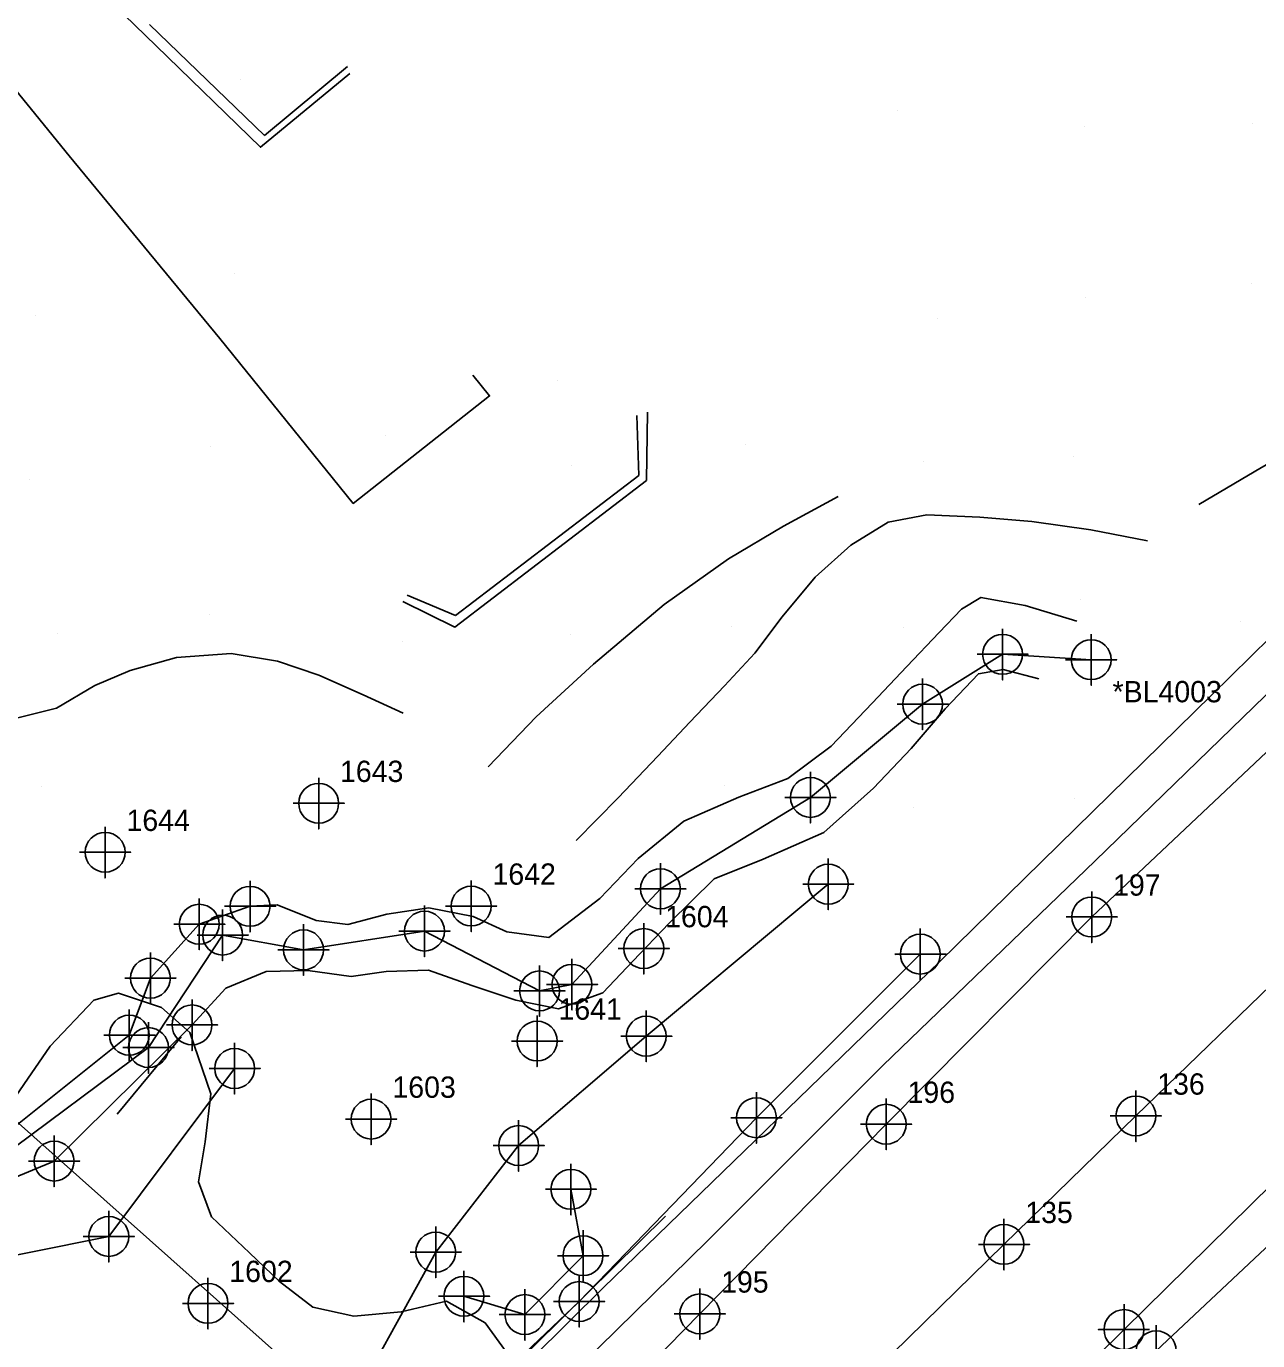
# Model space of a CAD drawing. Extents: x 1497074 to 1501343, y 481943 to 486114.
# Drawn here: x 1498304.9 to 1498449.4, y 484641.5 to 484795.7 of the extents above; entities that cross this region are included whole.
import ezdxf

# ---------------------------------------------------------------- set-up
doc = ezdxf.new("R2010")
doc.units = 0
for name, color, linetype in [('Exist DTM Breakline', 7, 'Continuous'), ('Exist DTM Breakline Cogo Point CELL', 7, 'Continuous'), ('Exist DTM Crownline', 7, 'Continuous'), ('Exist DTM Crownline Cogo Number', 7, 'Continuous'), ('Exist DTM Crownline Cogo Point CELL', 7, 'Continuous'), ('Exist DTM Drainline', 7, 'Continuous'), ('Exist DTM Drainline Cogo Comment', 7, 'Continuous'), ('Exist DTM Drainline Cogo Point CELL', 7, 'Continuous'), ('Exist DTM Regular Point CELL', 7, 'Continuous'), ('Exist DTM Regular Point Cogo Number', 7, 'Continuous'), ('Exist Guardrail', 7, 'Continuous'), ('Exist Roads EOP', 7, 'Continuous'), ('Exist Roads EOP Cogo Number', 7, 'Continuous'), ('Exist Roads EOP Cogo Point CELL', 7, 'Continuous'), ('Exist Roads EOT', 7, 'Continuous'), ('Exist Roads EOT Cogo Point CELL', 7, 'Continuous'), ('PH Exist DTM Boundary', 7, 'Continuous'), ('PH Exist DTM Breakline', 7, 'Continuous'), ('PH Exist DTM Obscure Area', 7, 'Continuous'), ('PH Exist DTM Point', 7, 'Continuous')]:
    doc.layers.add(name, color=color, linetype=linetype)

msp = doc.modelspace()

# ---------------------------------------------------------------- linework, layer by layer
at = {"layer": 'Exist DTM Breakline'}
for points in [[(1498398.97, 484695.06), (1498377.62, 484677.22), (1498362.65, 484664.38), (1498352.92, 484651.88), (1498341.4, 484630.97), (1498319.66, 484605.39), (1498294.63, 484580.7), (1498267.47, 484556.87), (1498247.84, 484542.39), (1498225.77, 484518.58)], [(1498282.88, 484689.25), (1498293.31, 484665.67), (1498300.1, 484663.88), (1498316.97, 484677.34), (1498319.45, 484684.03), (1498325.18, 484690.36), (1498331.14, 484692.46)], [(1498231.12, 484516.09), (1498254.57, 484537.6), (1498277.62, 484558.98), (1498300.74, 484581.31), (1498327.42, 484605.51), (1498348.5, 484625.92), (1498369.75, 484646.08), (1498390.54, 484667.65), (1498409.77, 484686.85)], [(1498324.33, 484678.54), (1498308.15, 484662.56), (1498298.41, 484658.52), (1498293.57, 484658), (1498288.84, 484660.48), (1498279.47, 484663.46)], [(1498269.6, 484655.18), (1498295.66, 484649.92), (1498314.57, 484653.72), (1498329.33, 484673.43)], [(1498467.53, 484668.57), (1498437.44, 484640.31), (1498419.38, 484622.3)], [(1498368.78, 484659.25), (1498370.2, 484651.46), (1498363.38, 484644.55), (1498356.23, 484646.7)]]:
    msp.add_lwpolyline(points, dxfattribs=at)
at = {"layer": 'Exist DTM Breakline Cogo Point CELL'}
for points in [[(1498398.97, 484698.06), (1498398.97, 484692.06), (1498398.97, 484695.06), (1498401.97, 484695.06), (1498395.97, 484695.06)], [(1498331.14, 484695.46), (1498331.14, 484689.46), (1498331.14, 484692.46), (1498334.14, 484692.46), (1498328.14, 484692.46)], [(1498325.18, 484693.36), (1498325.18, 484687.36), (1498325.18, 484690.36), (1498328.18, 484690.36), (1498322.18, 484690.36)], [(1498409.77, 484689.85), (1498409.77, 484683.85), (1498409.77, 484686.85), (1498412.77, 484686.85), (1498406.77, 484686.85)], [(1498319.45, 484687.03), (1498319.45, 484681.03), (1498319.45, 484684.03), (1498322.45, 484684.03), (1498316.45, 484684.03)], [(1498316.97, 484680.34), (1498316.97, 484674.34), (1498316.97, 484677.34), (1498319.97, 484677.34), (1498313.97, 484677.34)], [(1498324.33, 484681.54), (1498324.33, 484675.54), (1498324.33, 484678.54), (1498327.33, 484678.54), (1498321.33, 484678.54)], [(1498377.62, 484680.22), (1498377.62, 484674.22), (1498377.62, 484677.22), (1498380.62, 484677.22), (1498374.62, 484677.22)], [(1498329.33, 484676.43), (1498329.33, 484670.43), (1498329.33, 484673.43), (1498332.33, 484673.43), (1498326.33, 484673.43)], [(1498390.54, 484670.65), (1498390.54, 484664.65), (1498390.54, 484667.65), (1498393.54, 484667.65), (1498387.54, 484667.65)], [(1498362.65, 484667.38), (1498362.65, 484661.38), (1498362.65, 484664.38), (1498365.65, 484664.38), (1498359.65, 484664.38)], [(1498308.15, 484665.56), (1498308.15, 484659.56), (1498308.15, 484662.56), (1498311.15, 484662.56), (1498305.15, 484662.56)], [(1498368.78, 484662.25), (1498368.78, 484656.25), (1498368.78, 484659.25), (1498371.78, 484659.25), (1498365.78, 484659.25)], [(1498314.57, 484656.72), (1498314.57, 484650.72), (1498314.57, 484653.72), (1498317.57, 484653.72), (1498311.57, 484653.72)], [(1498352.92, 484654.88), (1498352.92, 484648.88), (1498352.92, 484651.88), (1498355.92, 484651.88), (1498349.92, 484651.88)], [(1498370.2, 484654.46), (1498370.2, 484648.46), (1498370.2, 484651.46), (1498373.2, 484651.46), (1498367.2, 484651.46)], [(1498356.23, 484649.7), (1498356.23, 484643.7), (1498356.23, 484646.7), (1498359.23, 484646.7), (1498353.23, 484646.7)], [(1498369.75, 484649.08), (1498369.75, 484643.08), (1498369.75, 484646.08), (1498372.75, 484646.08), (1498366.75, 484646.08)], [(1498363.38, 484647.55), (1498363.38, 484641.55), (1498363.38, 484644.55), (1498366.38, 484644.55), (1498360.38, 484644.55)], [(1498437.44, 484643.31), (1498437.44, 484637.31), (1498437.44, 484640.31), (1498440.44, 484640.31), (1498434.44, 484640.31)]]:
    msp.add_lwpolyline(points, dxfattribs=at)
for centre in [(1498398.97, 484695.06), (1498331.14, 484692.46), (1498325.18, 484690.36), (1498409.77, 484686.85), (1498319.45, 484684.03), (1498324.33, 484678.54), (1498316.97, 484677.34), (1498377.62, 484677.22), (1498329.33, 484673.43), (1498390.54, 484667.65), (1498362.65, 484664.38), (1498308.15, 484662.56), (1498368.78, 484659.25), (1498314.57, 484653.72), (1498352.92, 484651.88), (1498370.2, 484651.46), (1498356.23, 484646.7), (1498369.75, 484646.08), (1498363.38, 484644.55), (1498437.44, 484640.31)]:
    msp.add_circle(centre, 2.34, dxfattribs=at)
at = {"layer": 'Exist DTM Crownline'}
msp.add_lwpolyline([(1498174.51, 484418.76), (1498211.76, 484454.63), (1498248.88, 484490.3), (1498287.28, 484525.89), (1498324.11, 484560.63), (1498360.29, 484595.61), (1498397.16, 484630.83), (1498419.58, 484652.79), (1498435.06, 484667.86), (1498471.56, 484703.24), (1498507.82, 484739.07), (1498544.95, 484775.1), (1498579.44, 484811.19), (1498593.31, 484825.81), (1498614.8, 484848.72), (1498648.9, 484888.1), (1498682.16, 484928.34), (1498714.31, 484969.37), (1498734.43, 484994.62)], dxfattribs=at)
at = {"layer": 'Exist DTM Crownline Cogo Point CELL'}
for points in [[(1498435.06, 484670.86), (1498435.06, 484664.86), (1498435.06, 484667.86), (1498438.06, 484667.86), (1498432.06, 484667.86)], [(1498419.58, 484655.79), (1498419.58, 484649.79), (1498419.58, 484652.79), (1498422.58, 484652.79), (1498416.58, 484652.79)]]:
    msp.add_lwpolyline(points, dxfattribs=at)
for centre in [(1498435.06, 484667.86), (1498419.58, 484652.79)]:
    msp.add_circle(centre, 2.34, dxfattribs=at)
at = {"layer": 'Exist DTM Drainline'}
msp.add_lwpolyline([(1498429.82, 484721.4), (1498419.42, 484722.03), (1498410.04, 484716.18), (1498396.88, 484705.24), (1498379.28, 484694.51), (1498368.9, 484683.3), (1498365.1, 484682.53), (1498351.6, 484689.55), (1498337.41, 484687.35), (1498327.92, 484689.08), (1498319.22, 484675.88), (1498301.55, 484662.75), (1498296.33, 484661.35), (1498291.18, 484665.18), (1498283.03, 484681.58), (1498277.65, 484691.38)], dxfattribs=at)
at = {"layer": 'Exist DTM Drainline Cogo Point CELL'}
for points in [[(1498419.42, 484725.03), (1498419.42, 484719.03), (1498419.42, 484722.03), (1498422.42, 484722.03), (1498416.42, 484722.03)], [(1498429.82, 484724.4), (1498429.82, 484718.4), (1498429.82, 484721.4), (1498432.82, 484721.4), (1498426.82, 484721.4)], [(1498410.04, 484719.18), (1498410.04, 484713.18), (1498410.04, 484716.18), (1498413.04, 484716.18), (1498407.04, 484716.18)], [(1498396.88, 484708.24), (1498396.88, 484702.24), (1498396.88, 484705.24), (1498399.88, 484705.24), (1498393.88, 484705.24)], [(1498379.28, 484697.51), (1498379.28, 484691.51), (1498379.28, 484694.51), (1498382.28, 484694.51), (1498376.28, 484694.51)], [(1498327.92, 484692.08), (1498327.92, 484686.08), (1498327.92, 484689.08), (1498330.92, 484689.08), (1498324.92, 484689.08)], [(1498351.6, 484692.55), (1498351.6, 484686.55), (1498351.6, 484689.55), (1498354.6, 484689.55), (1498348.6, 484689.55)], [(1498337.41, 484690.35), (1498337.41, 484684.35), (1498337.41, 484687.35), (1498340.41, 484687.35), (1498334.41, 484687.35)], [(1498365.1, 484685.53), (1498365.1, 484679.53), (1498365.1, 484682.53), (1498368.1, 484682.53), (1498362.1, 484682.53)], [(1498368.9, 484686.3), (1498368.9, 484680.3), (1498368.9, 484683.3), (1498371.9, 484683.3), (1498365.9, 484683.3)], [(1498319.22, 484678.88), (1498319.22, 484672.88), (1498319.22, 484675.88), (1498322.22, 484675.88), (1498316.22, 484675.88)]]:
    msp.add_lwpolyline(points, dxfattribs=at)
for centre in [(1498419.42, 484722.03), (1498429.82, 484721.4), (1498410.04, 484716.18), (1498396.88, 484705.24), (1498379.28, 484694.51), (1498327.92, 484689.08), (1498351.6, 484689.55), (1498337.41, 484687.35), (1498368.9, 484683.3), (1498365.1, 484682.53), (1498319.22, 484675.88)]:
    msp.add_circle(centre, 2.34, dxfattribs=at)
at = {"layer": 'Exist DTM Regular Point CELL'}
for points in [[(1498339.19, 484707.55), (1498339.19, 484701.55), (1498339.19, 484704.55), (1498342.19, 484704.55), (1498336.19, 484704.55)], [(1498314.14, 484701.8), (1498314.14, 484695.8), (1498314.14, 484698.8), (1498317.14, 484698.8), (1498311.14, 484698.8)], [(1498357.08, 484695.49), (1498357.08, 484689.49), (1498357.08, 484692.49), (1498360.08, 484692.49), (1498354.08, 484692.49)], [(1498377.33, 484690.5), (1498377.33, 484684.5), (1498377.33, 484687.5), (1498380.33, 484687.5), (1498374.33, 484687.5)], [(1498364.82, 484679.65), (1498364.82, 484673.65), (1498364.82, 484676.65), (1498367.82, 484676.65), (1498361.82, 484676.65)], [(1498345.34, 484670.49), (1498345.34, 484664.49), (1498345.34, 484667.49), (1498348.34, 484667.49), (1498342.34, 484667.49)], [(1498326.2, 484648.87), (1498326.2, 484642.87), (1498326.2, 484645.87), (1498329.2, 484645.87), (1498323.2, 484645.87)]]:
    msp.add_lwpolyline(points, dxfattribs=at)
for centre in [(1498339.19, 484704.55), (1498314.14, 484698.8), (1498357.08, 484692.49), (1498377.33, 484687.5), (1498364.82, 484676.65), (1498345.34, 484667.49), (1498326.2, 484645.87)]:
    msp.add_circle(centre, 2.34, dxfattribs=at)
at = {"layer": 'Exist Guardrail'}
msp.add_line((1498379.88, 484656.12), (1498358.55, 484635.05), dxfattribs=at)
at = {"layer": 'Exist Roads EOP'}
msp.add_lwpolyline([(1498165.98, 484428.62), (1498180, 484442.69), (1498201.86, 484464.11), (1498239.3, 484499.9), (1498276.43, 484536.47), (1498313.13, 484573.18), (1498338.89, 484599.2), (1498349.09, 484609.46), (1498368.89, 484629.31), (1498383.9, 484644.63), (1498405.77, 484666.89), (1498429.88, 484691.21), (1498457.88, 484717.62), (1498496.23, 484753.16), (1498535.42, 484789.23), (1498556.84, 484809.01), (1498564.6, 484818.66), (1498566.38, 484823.54), (1498565.95, 484832.29), (1498567.61, 484834.53), (1498567.66, 484834.73)], dxfattribs=at)
at = {"layer": 'Exist Roads EOP Cogo Point CELL'}
for points in [[(1498429.88, 484694.21), (1498429.88, 484688.21), (1498429.88, 484691.21), (1498432.88, 484691.21), (1498426.88, 484691.21)], [(1498405.77, 484669.89), (1498405.77, 484663.89), (1498405.77, 484666.89), (1498408.77, 484666.89), (1498402.77, 484666.89)], [(1498383.9, 484647.63), (1498383.9, 484641.63), (1498383.9, 484644.63), (1498386.9, 484644.63), (1498380.9, 484644.63)]]:
    msp.add_lwpolyline(points, dxfattribs=at)
for centre in [(1498429.88, 484691.21), (1498405.77, 484666.89), (1498383.9, 484644.63)]:
    msp.add_circle(centre, 2.34, dxfattribs=at)
at = {"layer": 'Exist Roads EOT'}
msp.add_lwpolyline([(1498476.1, 484684.28), (1498463.39, 484672.07), (1498433.67, 484642.79), (1498415.98, 484625.26), (1498376.81, 484588.09)], dxfattribs=at)
at = {"layer": 'Exist Roads EOT Cogo Point CELL'}
msp.add_lwpolyline([(1498433.67, 484645.79), (1498433.67, 484639.79), (1498433.67, 484642.79), (1498430.67, 484642.79), (1498436.67, 484642.79)], dxfattribs=at)
msp.add_circle((1498433.67, 484642.79), 2.34, dxfattribs=at)
at = {"layer": 'PH Exist DTM Boundary'}
for points in [[(1498186.43, 484771.69), (1498560.82, 484438.23), (1498782.89, 484653.31), (1498924.23, 484841.06), (1498545.19, 485168.9), (1498406.94, 484985.26)], [(1497810.36, 484407.45), (1498181.14, 484070.49), (1498560.82, 484438.23), (1498186.43, 484771.69)]]:
    msp.add_lwpolyline(points, close=True, dxfattribs=at)
at = {"layer": 'PH Exist DTM Breakline'}
for p, q in [((1498332.85, 484782.92), (1498319.33, 484795.95)), ((1498342.56, 484790.99), (1498332.85, 484782.92)), ((1498376.51, 484750.06), (1498376.75, 484743)), ((1498376.75, 484743), (1498355.25, 484726.6)), ((1498355.25, 484726.6), (1498349.56, 484728.98))]:
    msp.add_line(p, q, dxfattribs=at)
for points in [[(1498359.22, 484628.11), (1498384.86, 484653.26), (1498405.36, 484673.77), (1498430.29, 484697.78), (1498443.63, 484710.75), (1498464.77, 484731.29), (1498490.84, 484757.11), (1498497.71, 484764.47), (1498519.45, 484785.49), (1498553.87, 484820.26), (1498564.01, 484831.41), (1498565.79, 484832.49)], [(1498357.29, 484754.77), (1498359.24, 484752.36), (1498343.24, 484739.73), (1498327.61, 484759.07), (1498309.91, 484780.52), (1498294.59, 484799.39), (1498283.42, 484812.17), (1498280.07, 484815.31), (1498276.09, 484818.03)], [(1498312.58, 484800.8), (1498320.11, 484793.44), (1498332.36, 484781.53), (1498342.85, 484790.18)], [(1498516.8, 484789.57), (1498514.61, 484786.75), (1498494.45, 484766.74), (1498466.99, 484739.94), (1498443.94, 484717.22), (1498412.06, 484686), (1498372.6, 484647.73), (1498355.93, 484631.24)], [(1498442.44, 484739.6), (1498449.8, 484743.97), (1498457.64, 484748.4), (1498465.41, 484752.75), (1498474.14, 484759.78), (1498487.03, 484768.95), (1498495.81, 484775.13), (1498502.49, 484779.15)], [(1498349.08, 484728.23), (1498355.15, 484725.22), (1498377.65, 484742.43), (1498377.77, 484750.43)], [(1498359.09, 484708.81), (1498364.69, 484714.7), (1498371.41, 484720.87), (1498379.71, 484727.88), (1498387.25, 484733.23), (1498393.71, 484737.06), (1498400.13, 484740.56)], [(1498436.42, 484735.34), (1498429.79, 484736.62), (1498422.85, 484737.62), (1498416.76, 484738.14), (1498410.55, 484738.38), (1498406.01, 484737.54), (1498401.63, 484734.84), (1498397.45, 484731.1), (1498393.58, 484726.43), (1498390.34, 484722.16), (1498386.79, 484718.33), (1498382.72, 484714.05), (1498378.97, 484710.09), (1498374.32, 484705.2), (1498369.41, 484700.19)], [(1498428.15, 484725.9), (1498422.08, 484727.77), (1498416.87, 484728.7), (1498414.6, 484727.34)], [(1498331.14, 484692.46), (1498334.32, 484692.65), (1498338.89, 484690.81), (1498342.61, 484690.31), (1498347.2, 484691.55), (1498352.11, 484692.3), (1498357.32, 484691.26), (1498361.26, 484689.45), (1498366.17, 484688.79), (1498372.19, 484693.36), (1498376.67, 484698.08), (1498382.01, 484702.44), (1498388.48, 484705.26), (1498394.22, 484707.46), (1498399.32, 484711.25), (1498404.12, 484716.3), (1498408.2, 484720.6), (1498411.99, 484724.59), (1498414.6, 484727.34)], [(1498269.88, 484709.47), (1498274.5, 484713.94), (1498279.79, 484716.29), (1498284.72, 484716.72), (1498290.58, 484715.56), (1498296.68, 484714.5), (1498302.03, 484714.12), (1498308.44, 484715.7), (1498312.94, 484718.37), (1498317.08, 484720.14), (1498322.49, 484721.64), (1498328.91, 484722.11), (1498334.34, 484721.22), (1498339.21, 484719.59), (1498344.41, 484717.28), (1498349.09, 484715.14)], [(1498423.67, 484719.14), (1498419.5, 484720.24), (1498416.58, 484719.75), (1498412.67, 484715.64), (1498408.68, 484710.97), (1498404.27, 484706.32), (1498398.45, 484701.12), (1498391.32, 484697.98), (1498385.58, 484695.68), (1498380.3, 484690.49), (1498376.05, 484686.02), (1498372.51, 484682.29), (1498367.34, 484680.43), (1498362.33, 484681.43), (1498357.15, 484683.16), (1498352.07, 484684.96), (1498347.1, 484684.81), (1498343.01, 484684.24), (1498337.91, 484684.94), (1498333.02, 484684.81), (1498328.28, 484682.86), (1498324.33, 484678.54)], [(1498323.04, 484677.13), (1498315.56, 484668.05)]]:
    msp.add_lwpolyline(points, dxfattribs=at)
at = {"layer": 'PH Exist DTM Obscure Area'}
for points in [[(1498307.67, 484676.05), (1498312.8, 484681.46), (1498315.7, 484682.25), (1498320.76, 484680.6), (1498324.07, 484677.66), (1498326.55, 484670.45), (1498325.86, 484664.83), (1498325.1, 484660.14), (1498326.63, 484656.03), (1498331.08, 484651.8), (1498334.61, 484648.45), (1498338.49, 484645.41), (1498343.32, 484644.37), (1498348.86, 484644.88), (1498354.17, 484646.11), (1498358.72, 484643.58), (1498361.19, 484640.19), (1498355.63, 484632.52)], [(1498355.63, 484632.52), (1498290.68, 484570.04), (1498257.3, 484537.58), (1498250.31, 484532.74), (1498247.22, 484535.69), (1498242.12, 484540.68), (1498249.39, 484548.29), (1498258.26, 484557.58), (1498264.88, 484564.52), (1498267.78, 484576.18), (1498266.58, 484587.34), (1498261.75, 484599.27), (1498263.15, 484609.32), (1498271.1, 484617.66), (1498279.29, 484626.23), (1498284.85, 484632.06), (1498282.05, 484639.76), (1498283.05, 484646.51), (1498293.08, 484654.8), (1498307.67, 484676.05)]]:
    msp.add_lwpolyline(points, dxfattribs=at)
at = {"layer": 'PH Exist DTM Point'}
for p, q in [((1498330.05, 484789.49), (1498330.05, 484789.49)), ((1498407.05, 484785.89), (1498407.05, 484785.89)), ((1498429.06, 484783.97), (1498429.06, 484783.97)), ((1498448.72, 484784.29), (1498448.72, 484784.29)), ((1498329.32, 484766.75), (1498329.32, 484766.75)), ((1498448.57, 484765.59), (1498448.57, 484765.59)), ((1498429.1, 484763.94), (1498429.1, 484763.94)), ((1498305.96, 484761.82), (1498305.96, 484761.82)), ((1498411.79, 484761.41), (1498411.79, 484761.41)), ((1498367.16, 484754.2), (1498367.16, 484754.2)), ((1498347.03, 484747.71), (1498347.03, 484747.71)), ((1498326.51, 484746.39), (1498326.51, 484746.39)), ((1498389.21, 484746.63), (1498389.21, 484746.63)), ((1498427.73, 484745.24), (1498427.73, 484745.24)), ((1498368.82, 484744.16), (1498368.82, 484744.16)), ((1498410.18, 484744.69), (1498410.18, 484744.69)), ((1498305.28, 484742.49), (1498305.28, 484742.49)), ((1498428.59, 484728.43), (1498428.59, 484728.43)), ((1498326.43, 484726.73), (1498326.43, 484726.73)), ((1498387.63, 484725.34), (1498387.63, 484725.34)), ((1498407.81, 484725.16), (1498407.81, 484725.16)), ((1498447.28, 484725.93), (1498447.28, 484725.93)), ((1498308.51, 484724.5), (1498308.51, 484724.5)), ((1498349.05, 484723.53), (1498349.05, 484723.53)), ((1498368.7, 484724.31), (1498368.7, 484724.31)), ((1498386.83, 484706.69), (1498386.83, 484706.69)), ((1498306.63, 484706.53), (1498306.63, 484706.53)), ((1498427.81, 484705.16), (1498427.81, 484705.16)), ((1498408.97, 484704.06), (1498408.97, 484704.06)), ((1498406.89, 484686.64), (1498406.89, 484686.64)), ((1498325, 484643.26), (1498325, 484643.26))]:
    msp.add_line(p, q, dxfattribs=at)

# ---------------------------------------------------------------- texts
at = {"layer": 'Exist DTM Crownline Cogo Number'}
for s, p in [('136', (1498437.56, 484670.36)), ('135', (1498422.08, 484655.29))]:
    msp.add_text(s, height=2.5, dxfattribs=at).set_placement(p)
at = {"layer": 'Exist DTM Drainline Cogo Comment'}
msp.add_text('*BL4003', height=2.5, dxfattribs=at).set_placement((1498432.32, 484716.4))
at = {"layer": 'Exist DTM Regular Point Cogo Number'}
for s, p in [('1643', (1498341.69, 484707.05)), ('1644', (1498316.64, 484701.3)), ('1642', (1498359.58, 484694.99)), ('1604', (1498379.83, 484690)), ('1641', (1498367.32, 484679.15)), ('1603', (1498347.84, 484669.99)), ('1602', (1498328.7, 484648.37))]:
    msp.add_text(s, height=2.5, dxfattribs=at).set_placement(p)
at = {"layer": 'Exist Roads EOP Cogo Number'}
for s, p in [('197', (1498432.38, 484693.71)), ('196', (1498408.27, 484669.39)), ('195', (1498386.4, 484647.13))]:
    msp.add_text(s, height=2.5, dxfattribs=at).set_placement(p)

doc.saveas('drawing.dxf')
